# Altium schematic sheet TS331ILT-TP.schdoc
size 127 x 101 mm
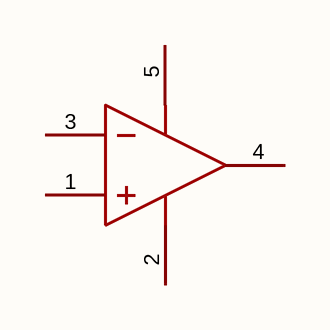
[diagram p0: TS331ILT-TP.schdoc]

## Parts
U?  ts331ilt-tp  [SOT-23-5_L2.9-W1.6-P0.95-LS2.8-BR_1]  (value not drawn)

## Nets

Not connected (* = marked no-connect by the designer): U? 1(+IN) 2(V-) 3(-IN) 4(OUT) 5(V+)

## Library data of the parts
U? = ts331ilt-tp: 输入失调电压(Vos):800uV;输入偏置电流(Ib):2pA;; Manufacturer: TECH PUBLIC(台舟); AddInBom: yes; ModelId: 25b054d4db3343b88aee285a0a719589; ModelTransform: 110.236,114.173,0,0,0,0,0.945,-2.44,0; Vos - Input Offset Voltage: 800uV; Ib - Input Bias Current: 2pA; Output Type: 开漏; Quiescent Current: 29uA；50uA; Maximum Power Supply Range (Vdd-Vss): 7V; Single Supply: 1.8V~5.5V; Input Offset Voltage Drift(Vos TC): 0.8uV/℃; Input Offset Current(Ios): 1pA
